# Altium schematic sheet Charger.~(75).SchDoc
size A3; SheetNumber: 2; SheetTotal: 2
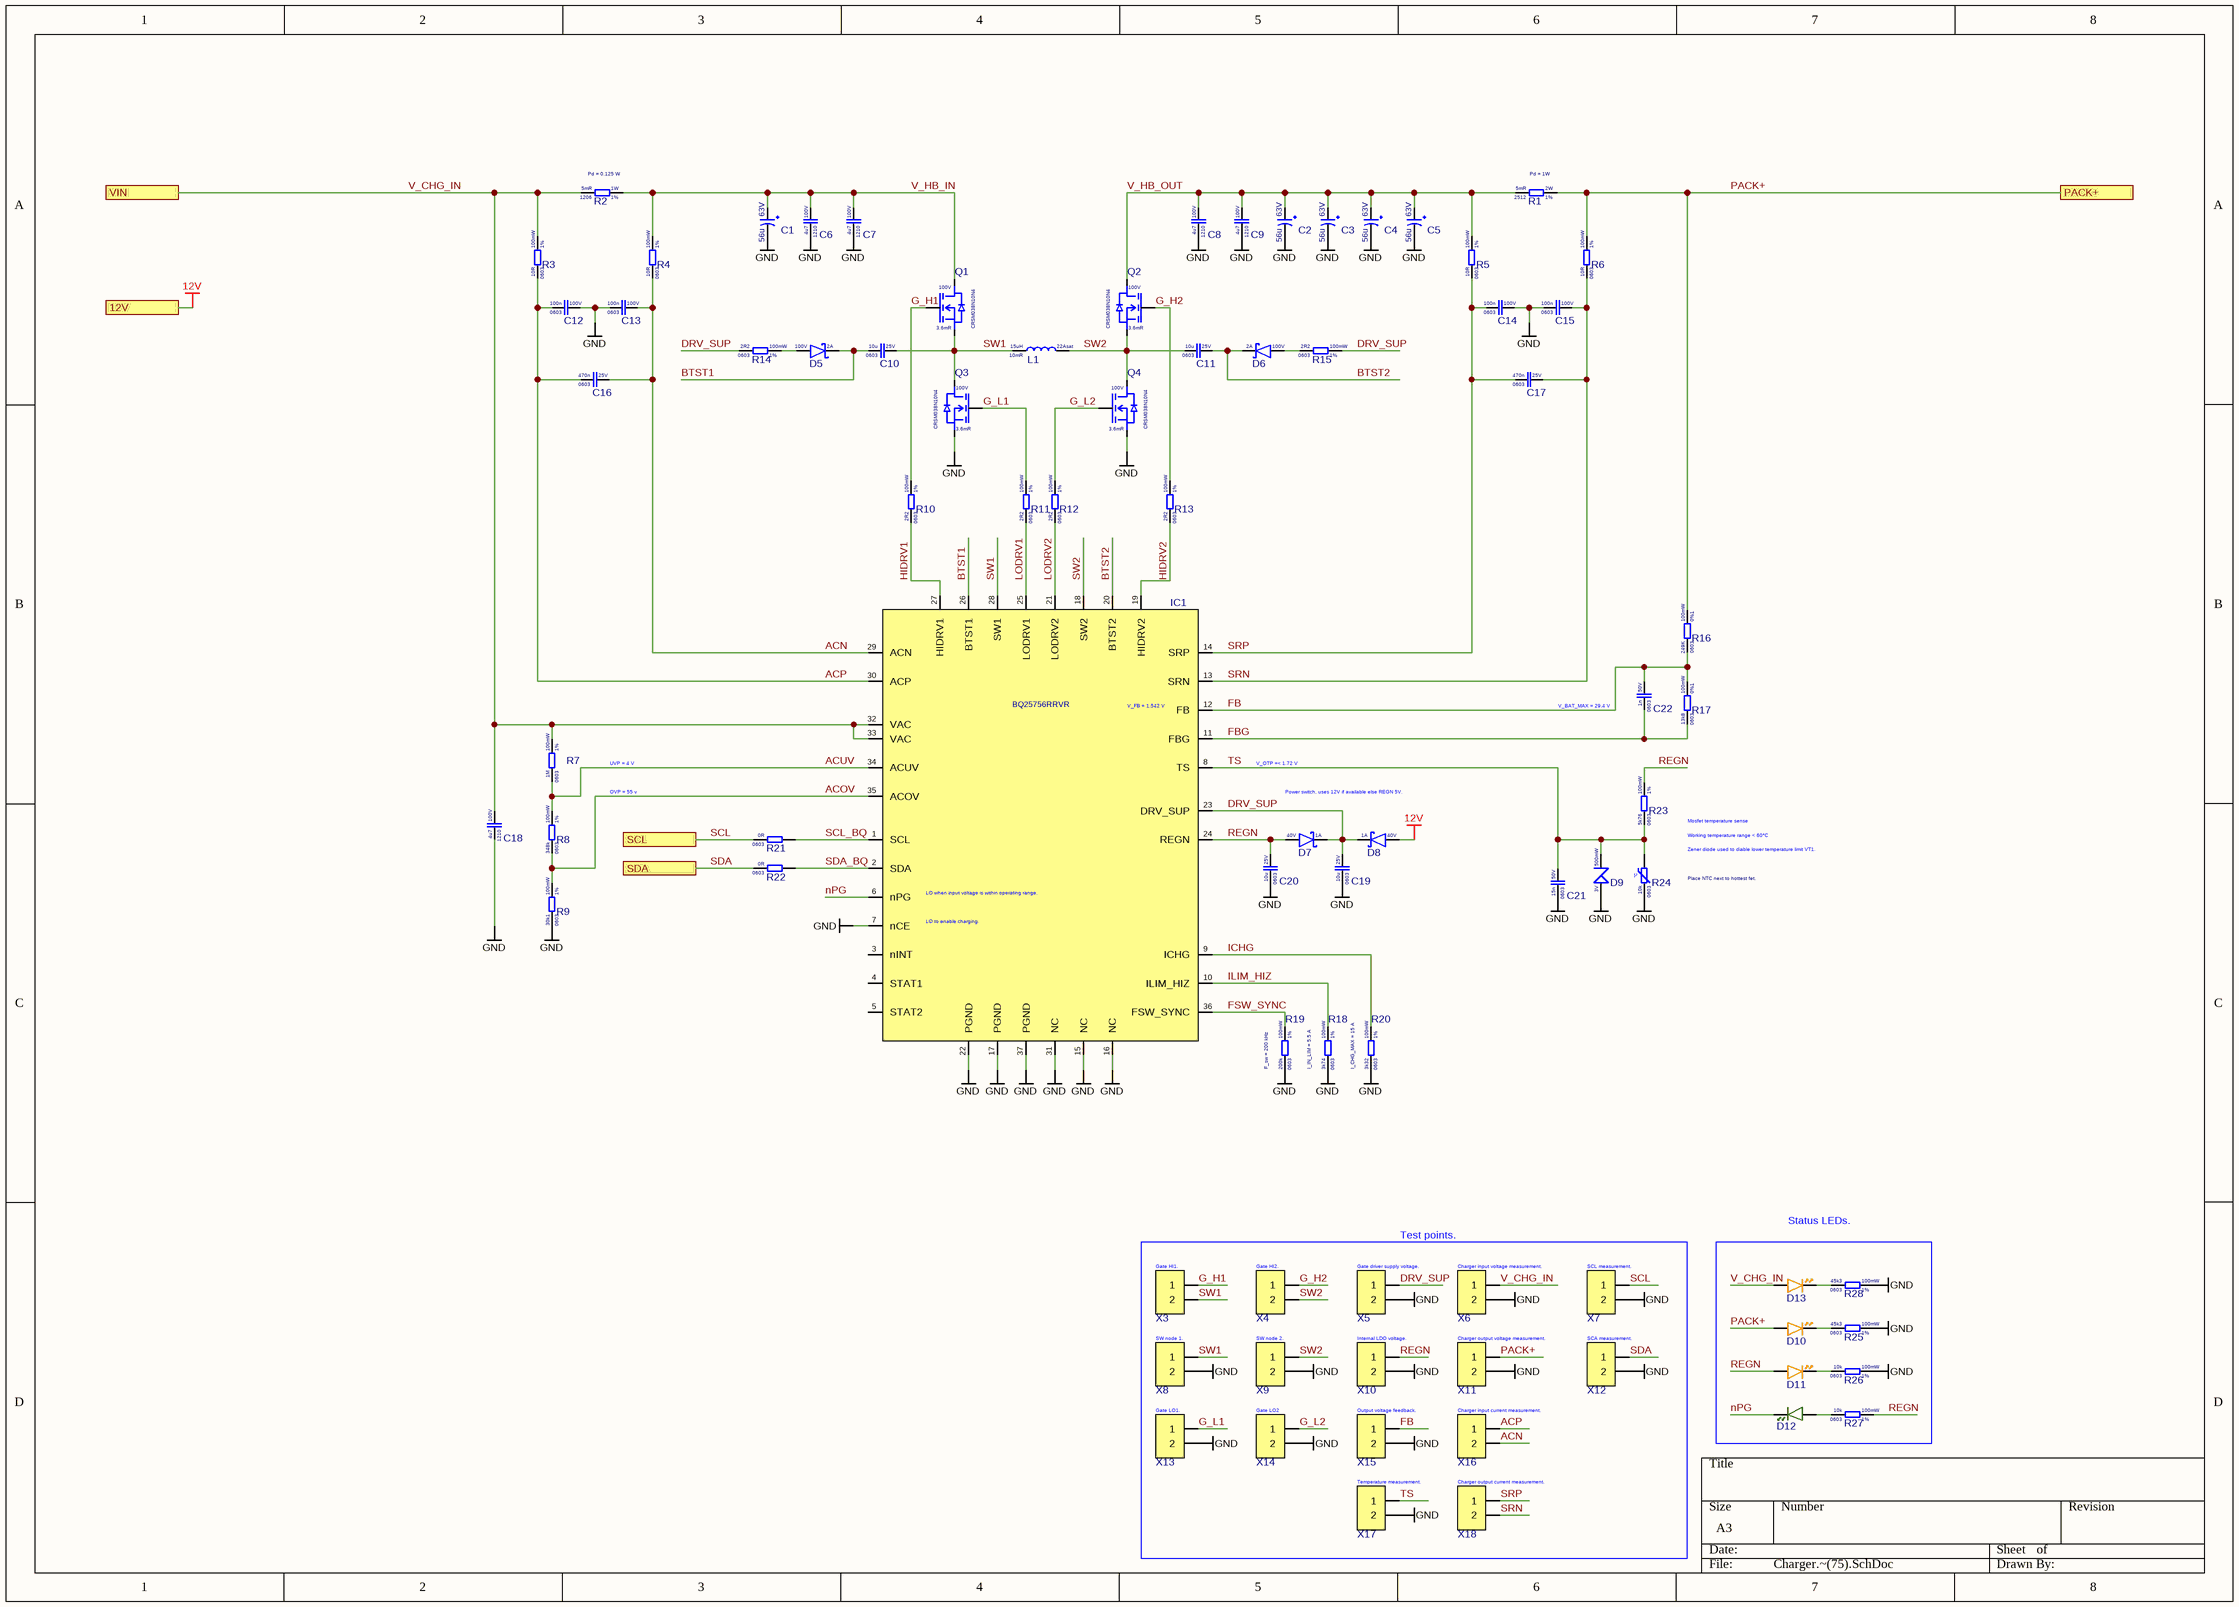
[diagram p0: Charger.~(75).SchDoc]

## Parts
C1  Voltage Rating: 63V  Capacitance: 56u  [CAP_SMD_10X10.2]  (hidden comment: EEHZA1J560P)
C2  Voltage Rating: 63V  Capacitance: 56u  [CAP_SMD_10X10.2]  (hidden comment: EEHZA1J560P)
C3  Voltage Rating: 63V  Capacitance: 56u  [CAP_SMD_10X10.2]  (hidden comment: EEHZA1J560P)
C4  Voltage Rating: 63V  Capacitance: 56u  [CAP_SMD_10X10.2]  (hidden comment: EEHZA1J560P)
C5  Voltage Rating: 63V  Capacitance: 56u  [CAP_SMD_10X10.2]  (hidden comment: EEHZA1J560P)
C6  Voltage Rating: 100V  Case Code (Imperial): 1210  Capacitance: 4u7  [CAP_1210]  (hidden comment: HMK325C7475KN-TE)
C7  Voltage Rating: 100V  Case Code (Imperial): 1210  Capacitance: 4u7  [CAP_1210]  (hidden comment: HMK325C7475KN-TE)
C8  Voltage Rating: 100V  Case Code (Imperial): 1210  Capacitance: 4u7  [CAP_1210]  (hidden comment: HMK325C7475KN-TE)
C9  Voltage Rating: 100V  Case Code (Imperial): 1210  Capacitance: 4u7  [CAP_1210]  (hidden comment: HMK325C7475KN-TE)
C10  Voltage Rating: 25V  Case Code (Imperial): 0603  Capacitance: 10u  [CAP 0603]  (hidden comment: CL10A106MA8NRNC)
C11  Voltage Rating: 25V  Case Code (Imperial): 0603  Capacitance: 10u  [CAP 0603]  (hidden comment: CL10A106MA8NRNC)
C12  Voltage Rating: 100V  Case Code (Imperial): 0603  Capacitance: 100n  [CAP 0603]  (hidden comment: CC0603KRX7R0BB104)
C13  Voltage Rating: 100V  Case Code (Imperial): 0603  Capacitance: 100n  [CAP 0603]  (hidden comment: CC0603KRX7R0BB104)
C14  Voltage Rating: 100V  Case Code (Imperial): 0603  Capacitance: 100n  [CAP 0603]  (hidden comment: CC0603KRX7R0BB104)
C15  Voltage Rating: 100V  Case Code (Imperial): 0603  Capacitance: 100n  [CAP 0603]  (hidden comment: CC0603KRX7R0BB104)
C16  Voltage Rating: 25V  Case Code (Imperial): 0603  Capacitance: 470n  [CAP 0603]  (hidden comment: CL10B474KA8NNNC)
C17  Voltage Rating: 25V  Case Code (Imperial): 0603  Capacitance: 470n  [CAP 0603]  (hidden comment: CL10B474KA8NNNC)
C18  Voltage Rating: 100V  Case Code (Imperial): 1210  Capacitance: 4u7  [CAP_1210]  (hidden comment: HMK325C7475KN-TE)
C19  Voltage Rating: 25V  Case Code (Imperial): 0603  Capacitance: 10u  [CAP 0603]  (hidden comment: CL10A106MA8NRNC)
C20  Voltage Rating: 25V  Case Code (Imperial): 0603  Capacitance: 10u  [CAP 0603]  (hidden comment: CL10A106MA8NRNC)
C21  Voltage Rating: 50V  Case Code (Imperial): 0603  Capacitance: 15n  [CAP 0603]  (hidden comment: CC0603KRX7R9BB153)
C22  Voltage Rating: 50V  Case Code (Imperial): 0603  Capacitance: 1n  [CAP 0603]  (hidden comment: CL10B102KB8NNNC)
D5  Forward Current: 2A  Reverse Voltage: 100V  [SMAF]  (hidden comment: SS210F)
D6  Forward Current: 2A  Reverse Voltage: 100V  [SMAF]  (hidden comment: SS210F)
D7  Forward Current: 1A  Reverse Voltage: 40V  [SOD-323]  (hidden comment: 1N5819WS)
D8  Forward Current: 1A  Reverse Voltage: 40V  [SOD-323]  (hidden comment: 1N5819WS)
D9  Power Rating: 500mW  Reverse Voltage: 3V  [SOD-123]  (hidden comment: BZT52C3V0)
D10  XL-1608UOC-06  [DIODE_0603]  (value not drawn)
D11  XL-1608UOC-06  [DIODE_0603]  (value not drawn)
D12  PSC-1608U52GC-G4  [DIODE_0603]  (value not drawn)
D13  XL-1608UOC-06  [DIODE_0603]  (value not drawn)
IC1  BQ25756RRVR  [VQFN-36(5x6)]
L1  Resistance: 10mR  Saturation current: 22Asat  Inductance: 15uH  [MTF1810-150M]  (hidden comment: MTF1810-150M)
Q1  Rds: 3.6mR  Voltage: 100V  [DFN-8 (5x6)]  (hidden comment: CRSM038N10N4)
Q2  Rds: 3.6mR  Voltage: 100V  [DFN-8 (5x6)]  (hidden comment: CRSM038N10N4)
Q3  Rds: 3.6mR  Voltage: 100V  [DFN-8 (5x6)]  (hidden comment: CRSM038N10N4)
Q4  Rds: 3.6mR  Voltage: 100V  [DFN-8 (5x6)]  (hidden comment: CRSM038N10N4)
R1  Pd = 1W  Resistance Tolerance: 1%  Resistance: 5mR  Power Rating: 2W  Case Code (Imperial): 2512  [RES_2512]
R2  Pd = 0.125 W  Resistance Tolerance: 1%  Resistance: 5mR  Power Rating: 1W  Case Code (Imperial): 1206  [RES_1206]
R3  Resistance Tolerance: 1%  Resistance: 10R  Power Rating: 100mW  Case Code (Imperial): 0603  [RES_0603]  (hidden comment: 0603WAF100JT5E)
R4  Resistance Tolerance: 1%  Resistance: 10R  Power Rating: 100mW  Case Code (Imperial): 0603  [RES_0603]  (hidden comment: 0603WAF100JT5E)
R5  Resistance Tolerance: 1%  Resistance: 10R  Power Rating: 100mW  Case Code (Imperial): 0603  [RES_0603]  (hidden comment: 0603WAF100JT5E)
R6  Resistance Tolerance: 1%  Resistance: 10R  Power Rating: 100mW  Case Code (Imperial): 0603  [RES_0603]  (hidden comment: 0603WAF100JT5E)
R7  Resistance Tolerance: 1%  Resistance: 1M  Power Rating: 100mW  Case Code (Imperial): 0603  [RES_0603]  (hidden comment: 0603WAF1004T5E)
R8  Resistance Tolerance: 1%  Resistance: 348k  Power Rating: 100mW  Case Code (Imperial): 0603  [RES_0603]  (hidden comment: 0603WAF3483T5E)
R9  Resistance Tolerance: 1%  Resistance: 30k1  Power Rating: 100mW  Case Code (Imperial): 0603  [RES_0603]  (hidden comment: 0603WAF3012T5E)
R10  Resistance Tolerance: 1%  Resistance: 2R2  Power Rating: 100mW  Case Code (Imperial): 0603  [RES_0603]  (hidden comment: 0603WAF220KT5E)
R11  Resistance Tolerance: 1%  Resistance: 2R2  Power Rating: 100mW  Case Code (Imperial): 0603  [RES_0603]  (hidden comment: 0603WAF220KT5E)
R12  Resistance Tolerance: 1%  Resistance: 2R2  Power Rating: 100mW  Case Code (Imperial): 0603  [RES_0603]  (hidden comment: 0603WAF220KT5E)
R13  Resistance Tolerance: 1%  Resistance: 2R2  Power Rating: 100mW  Case Code (Imperial): 0603  [RES_0603]  (hidden comment: 0603WAF220KT5E)
R14  Resistance Tolerance: 1%  Resistance: 2R2  Power Rating: 100mW  Case Code (Imperial): 0603  [RES_0603]  (hidden comment: 0603WAF220KT5E)
R15  Resistance Tolerance: 1%  Resistance: 2R2  Power Rating: 100mW  Case Code (Imperial): 0603  [RES_0603]  (hidden comment: 0603WAF220KT5E)
R16  Resistance Tolerance: 0%1  Resistance: 249K  Power Rating: 100mW  Case Code (Imperial): 0603  [RES_0603]  (hidden comment: RT0603BRD07249KL)
R17  Resistance Tolerance: 0%1  Resistance: 13k8  Power Rating: 100mW  Case Code (Imperial): 0603  [RES_0603]  (hidden comment: RT0603BRD0713K8L)
R18  I_IN_LIM = 5.5 A  Resistance Tolerance: 1%  Resistance: 3k74  Power Rating: 100mW  Case Code (Imperial): 0603  [RES_0603]
R19  F_sw = 200 kHz  Resistance Tolerance: 1%  Resistance: 200k  Power Rating: 100mW  Case Code (Imperial): 0603  [RES_0603]
R20  I_CHG_MAX = 15 A  Resistance Tolerance: 1%  Resistance: 3k32  Power Rating: 100mW  Case Code (Imperial): 0603  [RES_0603]
R21  Resistance: 0R  Case Code (Imperial): 0603  [RES_0603]  (hidden comment: 0603WAF0000T5E)
R22  Resistance: 0R  Case Code (Imperial): 0603  [RES_0603]  (hidden comment: 0603WAF0000T5E)
R23  Resistance Tolerance: 1%  Resistance: 5k76  Power Rating: 100mW  Case Code (Imperial): 0603  [RES_0603]  (hidden comment: 0603WAF5761T5E)
R24  Place NTC next to hottest fet.  Resistance: 10k  Case Code (Imperial): 0603  [RES_0603]
R25  Resistance Tolerance: 1%  Resistance: 45k3  Power Rating: 100mW  Case Code (Imperial): 0603  [RES_0603]  (hidden comment: 0603WAF4532T5E)
R26  Resistance Tolerance: 1%  Resistance: 10k  Power Rating: 100mW  Case Code (Imperial): 0603  [RES_0603]  (hidden comment: 0603WAF1002T5E)
R27  Resistance Tolerance: 1%  Resistance: 10k  Power Rating: 100mW  Case Code (Imperial): 0603  [RES_0603]  (hidden comment: 0603WAF1002T5E)
R28  Resistance Tolerance: 1%  Resistance: 45k3  Power Rating: 100mW  Case Code (Imperial): 0603  [RES_0603]  (hidden comment: 0603WAF4532T5E)
X3  ZX-PZ1.27-1-2PZZ  [Pin header 1x2 1.27mmP THT Vertical]  (value not drawn)
X4  ZX-PZ1.27-1-2PZZ  [Pin header 1x2 1.27mmP THT Vertical]  (value not drawn)
X5  ZX-PZ1.27-1-2PZZ  [Pin header 1x2 1.27mmP THT Vertical]  (value not drawn)
X6  ZX-PZ1.27-1-2PZZ  [Pin header 1x2 1.27mmP THT Vertical]  (value not drawn)
X7  ZX-PZ1.27-1-2PZZ  [Pin header 1x2 1.27mmP THT Vertical]  (value not drawn)
X8  ZX-PZ1.27-1-2PZZ  [Pin header 1x2 1.27mmP THT Vertical]  (value not drawn)
X9  ZX-PZ1.27-1-2PZZ  [Pin header 1x2 1.27mmP THT Vertical]  (value not drawn)
X10  ZX-PZ1.27-1-2PZZ  [Pin header 1x2 1.27mmP THT Vertical]  (value not drawn)
X11  ZX-PZ1.27-1-2PZZ  [Pin header 1x2 1.27mmP THT Vertical]  (value not drawn)
X12  ZX-PZ1.27-1-2PZZ  [Pin header 1x2 1.27mmP THT Vertical]  (value not drawn)
X13  ZX-PZ1.27-1-2PZZ  [Pin header 1x2 1.27mmP THT Vertical]  (value not drawn)
X14  ZX-PZ1.27-1-2PZZ  [Pin header 1x2 1.27mmP THT Vertical]  (value not drawn)
X15  ZX-PZ1.27-1-2PZZ  [Pin header 1x2 1.27mmP THT Vertical]  (value not drawn)
X16  ZX-PZ1.27-1-2PZZ  [Pin header 1x2 1.27mmP THT Vertical]  (value not drawn)
X17  ZX-PZ1.27-1-2PZZ  [Pin header 1x2 1.27mmP THT Vertical]  (value not drawn)
X18  ZX-PZ1.27-1-2PZZ  [Pin header 1x2 1.27mmP THT Vertical]  (value not drawn)

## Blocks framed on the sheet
Test points.: X3-X18
Status LEDs.: D10-D13 R25-R28

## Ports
12V (see Arhitecture[5B]), PACK+ (see Arhitecture[6B]), SCL (see Arhitecture[5B]), SDA (see Arhitecture[5B]), VIN (see Arhitecture[5B])

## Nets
12V: D8.A ; port 12V
GND: C1.- C2.- C3.- C4.- C5.- C6.1 C7.1 C8.1 C9.1 C12.2 C13.1 C14.2 C15.1 C18.1 C19.1 C20.1 C21.1 D9.A IC1.7(nCE) IC1.15(NC) IC1.16(NC) IC1.17(PGND) IC1.22(PGND) IC1.31(NC) IC1.37(PGND) Q3.S Q4.S R9.1 R18.1 R19.1 R20.1 R24.1 R25.2 R26.2 R28.2 X5.2 X6.2 X7.2 X8.2 X9.2 X10.2 X11.2 X12.2 X13.2 X14.2 X15.2 X17.2
ACN: C13.2 C16.2 IC1.29(ACN) R4.1 X16.2
ACOV: IC1.35(ACOV) R8.1 R9.2
ACP: C12.1 C16.1 IC1.30(ACP) R3.1 X16.1
ACUV: IC1.34(ACUV) R7.1 R8.2
BTST1: C10.1 D5.K IC1.26(BTST1)
BTST2: C11.2 D6.K IC1.20(BTST2)
DRV_SUP: C19.2 D7.K D8.K IC1.23(DRV_SUP) R14.1 R15.2 X5.1
FB: C22.2 IC1.12(FB) R16.1 R17.2 X15.1
FBG: C22.1 IC1.11(FBG) R17.1
FSW_SYNC: IC1.36(FSW_SYNC) R19.2
G_H1: Q1.G R10.2 X3.1
G_H2: Q2.G R13.2 X4.1
G_L1: Q3.G R11.2 X13.1
G_L2: Q4.G R12.2 X14.1
HIDRV1: IC1.27(HIDRV1) R10.1
HIDRV2: IC1.19(HIDRV2) R13.1
ICHG: IC1.9(ICHG) R20.2
ILIM_HIZ: IC1.10(ILIM_HIZ) R18.2
LODRV1: IC1.25(LODRV1) R11.1
LODRV2: IC1.21(LODRV2) R12.1
nPG: D12.K IC1.6(nPG)
PACK+: D10.A R1.2 R6.2 R16.2 X11.1 ; port PACK+
REGN: C20.2 D7.A D11.A IC1.24(REGN) R23.2 R27.2 X10.1
SCL: R21.1 X7.1 ; port SCL
SCL_BQ: IC1.1(SCL) R21.2
SDA: R22.1 X12.1 ; port SDA
SDA_BQ: IC1.2(SDA) R22.2
SRN: C15.2 C17.2 IC1.13(SRN) R6.1 X18.2
SRP: C14.1 C17.1 IC1.14(SRP) R5.1 X18.1
SW1: C10.2 IC1.28(SW1) L1.1 Q1.S Q3.D X3.2 X8.1
SW2: C11.1 IC1.18(SW2) L1.2 Q2.S Q4.D X4.2 X9.1
TS: C21.2 D9.K IC1.8(TS) R23.1 R24.2 X17.1
V_CHG_IN: C18.2 D13.A IC1.32(VAC) IC1.33(VAC) R2.1 R3.2 R7.2 X6.1 ; port VIN
V_HB_IN: C1.+ C6.2 C7.2 Q1.D R2.2 R4.2
V_HB_OUT: C2.+ C3.+ C4.+ C5.+ C8.2 C9.2 Q2.D R1.1 R5.2
NetD5_A: D5.A R14.2
NetD6_A: D6.A R15.1
NetD10_K: D10.K R25.1
NetD11_K: D11.K R26.1
NetD12_A: D12.A R27.1
NetD13_K: D13.K R28.1

Not connected (* = marked no-connect by the designer): IC1 3(nINT) 4(STAT1) 5(STAT2)

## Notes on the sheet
- UVP = 4 V
- (near IC1) V_FB = 1.542 V
- V_OTP =< 1.72 V
- (near C22) V_BAT_MAX = 29.4 V
- OVP = 55 v
- Power switch, uses 12V if available else REGN 5V.
- Mosfet temperature sense
- Working temperature range < 60°C
- (near IC1) LO when input voltage is within operating range.
- Zener diode used to diable lower temperature limit VT1.
- (near IC1) LO to enable charging.
- (near X3) Gate HI1.
- (near X4) Gate HI2.
- (near X5) Gate driver supply voltage.
- (near X6) Charger input voltage measurement.
- (near X7) SCL measurement.
- (near X8) SW node 1.
- (near X9) SW node 2.
- (near X10) Internal LDO voltage.
- (near X11) Charger output voltage measurement.
- (near X12) SCA measurement.
- (near X13) Gate LO1.
- (near X14) Gate LO2
- (near X15) Output voltage feedback.
- (near X16) Charger input current measurement.
- (near X17) Temperature measurement.
- (near X18) Charger output current measurement.

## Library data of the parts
C1-C5 = EEHZA1J560P: Cap AL-EL 56uF 63V 30mR 1.8Ar SMD 10x10.2mm; Manufacturer: Panasonic
C6-C9 C18 = HMK325C7475KN-TE: Cap 4.7uF 100V 1210 X7R; Manufacturer: Taiyo Yuden
C10 C11 C19 C20 = CL10A106MA8NRNC: Cap 10uF 25V 0603 X5R; Manufacturer: Samsung
C12-C15 = CC0603KRX7R0BB104: Cap 100nF 100V 0603 X7R; Manufacturer: YAGEO
C16 C17 = CL10B474KA8NNNC: Cap 470nF 25V 0603 X7R; Manufacturer: Samsung
C21 = CC0603KRX7R9BB153: Cap 15nF 50V 0603 X7R; Manufacturer: Yageo; Manufacturer Part Number: CC0603KRX7R9BB104
C22 = CL10B102KB8NNNC: Cap 1nF 50V 0603 X7R; Manufacturer: Samsung
D5 D6 = SS210F: Schottky 100V 2A 850mVf SMAF; Manufacturer: GOODWORK
D7 D8 = 1N5819WS: Schottky 40V 1A 600mVf SOD-323; Manufacturer: Guangdong Hottech
D9 = BZT52C3V0: Zener 3.0V 500mW SOD-123; Manufacturer: Shandong Jingdao Microelectronics
D10 D11 D13 = XL-1608UOC-06: LED Orange 0603 20mA; Manufacturer: XINGLIGHT
D12 = PSC-1608U52GC-G4: LED Green 0603 20mA; Manufacturer: HONGLITRONIC
IC1 = BQ25756RRVR: Charger IC; Manufacturer: Texas Instruments
L1 = MTF1810-150M: Inductor 15uH 22Asat 10mR SMD 18x18x9 mm; Manufacturer: COILMX
Q1-Q4 = CRSM038N10N4: Nmos 100V 100A 3.6mR DFN-8(5x6); Manufacturer: CRMICRO
R1 = RLM25FEER005: Res 5mR 2512 1% 2W; Manufacturer: TA-I Tech
R2 = FRM121WFR005TM: Res 5mR 1206 1% 1W; Manufacturer: FOJAN
R3-R6 = 0603WAF100JT5E: Res 10R 0603 1% 100mW 75V; Manufacturer: Uni-Royal
R7 = 0603WAF1004T5E: Res 1M 0603 1% 100mW 75V; Manufacturer: Uni-Royal
R8 = 0603WAF3483T5E: Res 348k 0603 1% 100mW 75V; Manufacturer: Uni-Royal
R9 = 0603WAF3012T5E: Res 30k1 0603 1% 100mW 75V; Manufacturer: Uni-Royal
R10-R15 = 0603WAF220KT5E: Res 2R2 0603 1% 100mW 75V; Manufacturer: Uni-Royal
R16 = RT0603BRD07249KL: Res 249K 0603 0.1% 100mW 75V; Manufacturer: YAGEO
R17 = RT0603BRD0713K8L: Res 13.8k 0603 0.1% 100mW 75V; Manufacturer: YAGEO
R18 = FRC0603F3741TS: Res 3K74 0603 1% 100mW 75V; Manufacturer: FOJAN
R19 = 0603WAF2003T5E: Res 200K 0603 1% 100mW 75V; Manufacturer: UNI-ROYAL
R20 = 0603WAF3321T5E: Res 3k32 0603 1% 100mW 75V; Manufacturer: UNI-ROYAL
R21 R22 = 0603WAF0000T5E: Res 0R 0603 1% 100mW 75V; Manufacturer: UNI-ROYAL
R23 = 0603WAF5761T5E: Res 5k76 0603 1% 100mW 75V; Manufacturer: Uni-Royal
R24 = NCP18XH103F03RB: NTC 10k 0603 1% 3455K; Manufacturer: Murata
R25 R28 = 0603WAF4532T5E: Res 45k3 0603 1% 100mW 75V; Manufacturer: Uni-Royal
R26 R27 = 0603WAF1002T5E: Res 10k 0603 1% 100mW 75V; Manufacturer: Uni-Royal
X3-X18 = ZX-PZ1.27-1-2PZZ: Pin header 1x2 1.27mmP THT Vertical; Manufacturer: Megastar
